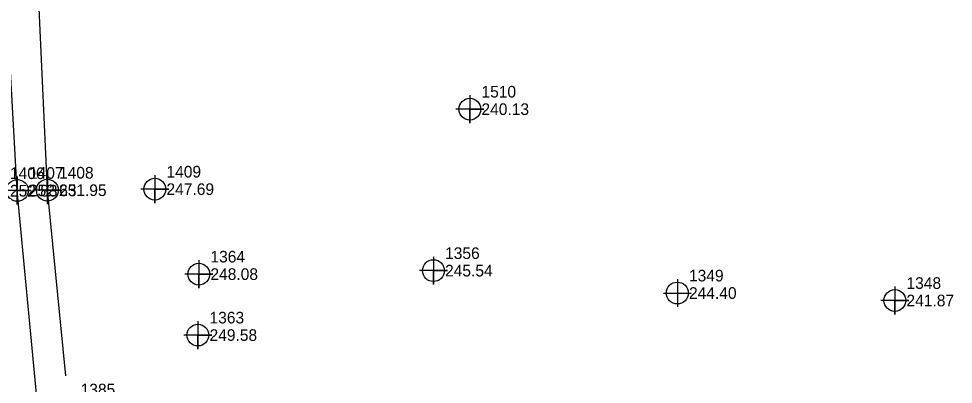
# Model space of a CAD drawing. Extents: x 2130962 to 2131465, y 643052 to 644206.
# Drawn here: x 2131260.2 to 2131460.9, y 643227.7 to 643306.2 of the extents above; entities that cross this region are included whole.
import ezdxf

# ---------------------------------------------------------------- set-up
doc = ezdxf.new("R2010")
doc.units = 0
for name, color, linetype in [('Exist DTM Breakline', 7, 'Continuous'), ('Exist DTM Breakline Cogo Elevation', 7, 'Continuous'), ('Exist DTM Breakline Cogo Number', 7, 'Continuous'), ('Exist DTM Breakline Cogo Point CELL', 7, 'Continuous'), ('Exist DTM Regular Point CELL', 7, 'Continuous'), ('Exist DTM Regular Point Cogo Elevation', 7, 'Continuous'), ('Exist DTM Regular Point Cogo Number', 7, 'Continuous'), ('Exist Roads EOP', 7, 'Continuous'), ('Exist Roads EOP Cogo Elevation', 7, 'Continuous'), ('Exist Roads EOP Cogo Number', 7, 'Continuous'), ('Exist Roads EOP Cogo Point CELL', 7, 'Continuous'), ('Exist Roads EOT Cogo Elevation', 7, 'Continuous'), ('Exist Roads EOT Cogo Number', 7, 'Continuous')]:
    doc.layers.add(name, color=color, linetype=linetype)

msp = doc.modelspace()

# ---------------------------------------------------------------- linework, layer by layer
at = {"layer": 'Exist DTM Breakline'}
msp.add_line((2131270.3119, 643229.444), (2131266.3306, 643269.372), dxfattribs=at)
msp.add_lwpolyline([(2131266.3306, 643269.372), (2131264.0776, 643319.4437), (2131258.8396, 643369.5498), (2131255.3671, 643419.5794), (2131249.6414, 643469.556), (2131244.7652, 643520.0623), (2131238.8778, 643569.4077), (2131228.6495, 643620.6699), (2131219.85, 643669.4823), (2131206.9682, 643717.8453), (2131195.8132, 643768.1497), (2131183.2404, 643816.8151), (2131169.0496, 643865.1461), (2131151.2314, 643913.4424), (2131130.7295, 643958.9736), (2131122.7411, 643983.0115)], dxfattribs=at)
at = {"layer": 'Exist DTM Breakline Cogo Point CELL'}
msp.add_lwpolyline([(2131266.3306, 643272.372), (2131266.3306, 643266.372), (2131266.3306, 643269.372), (2131269.3306, 643269.372), (2131263.3306, 643269.372)], dxfattribs=at)
msp.add_circle((2131266.3306, 643269.372), 2.344, dxfattribs=at)
at = {"layer": 'Exist DTM Regular Point CELL'}
for points in [[(2131357.0825, 643289.7878), (2131357.0825, 643283.7878), (2131357.0825, 643286.7878), (2131360.0825, 643286.7878), (2131354.0825, 643286.7878)], [(2131289.4176, 643272.5954), (2131289.4176, 643266.5954), (2131289.4176, 643269.5954), (2131292.4176, 643269.5954), (2131286.4176, 643269.5954)], [(2131298.8562, 643254.3369), (2131298.8562, 643248.3369), (2131298.8562, 643251.3369), (2131301.8562, 643251.3369), (2131295.8562, 643251.3369)], [(2131349.2628, 643255.0853), (2131349.2628, 643249.0853), (2131349.2628, 643252.0853), (2131352.2628, 643252.0853), (2131346.2628, 643252.0853)], [(2131401.6594, 643250.2687), (2131401.6594, 643247.2687)], [(2131398.6594, 643247.2687), (2131401.6594, 643247.2687)], [(2131401.6594, 643247.2687), (2131404.6594, 643247.2687)], [(2131401.6594, 643247.2687), (2131401.6594, 643244.2687)], [(2131448.3809, 643248.6638), (2131448.3809, 643242.6638), (2131448.3809, 643245.6638), (2131451.3809, 643245.6638), (2131445.3809, 643245.6638)], [(2131298.6665, 643241.234), (2131298.6665, 643235.234), (2131298.6665, 643238.234), (2131301.6665, 643238.234), (2131295.6665, 643238.234)]]:
    msp.add_lwpolyline(points, dxfattribs=at)
for centre in [(2131357.0825, 643286.7878), (2131289.4176, 643269.5954), (2131298.8562, 643251.3369), (2131349.2628, 643252.0853), (2131401.6594, 643247.2687), (2131448.3809, 643245.6638), (2131298.6665, 643238.234)]:
    msp.add_circle(centre, 2.344, dxfattribs=at)
at = {"layer": 'Exist Roads EOP'}
msp.add_lwpolyline([(2131264.2715, 643222.5647), (2131259.8757, 643269.3254), (2131257.0196, 643319.4043), (2131254.2561, 643369.6499), (2131250.0777, 643419.4187), (2131246.1511, 643469.0294), (2131240.8382, 643519.1271), (2131234.3674, 643568.5584), (2131226.3321, 643620.1808), (2131217.0271, 643668.7116), (2131205.6213, 643717.607), (2131192.0578, 643767.2595), (2131177.9714, 643815.0911), (2131162.2913, 643862.9344), (2131145.3604, 643910.8486), (2131126.9113, 643957.2915), (2131112.3691, 643996.1228)], dxfattribs=at)
at = {"layer": 'Exist Roads EOP Cogo Point CELL'}
msp.add_lwpolyline([(2131259.8757, 643272.3254), (2131259.8757, 643266.3254), (2131259.8757, 643269.3254), (2131262.8757, 643269.3254), (2131256.8757, 643269.3254)], dxfattribs=at)
msp.add_circle((2131259.8757, 643269.3254), 2.344, dxfattribs=at)

# ---------------------------------------------------------------- texts
at = {"layer": 'Exist DTM Breakline Cogo Elevation'}
msp.add_text('251.95', height=2.5, dxfattribs=at).set_placement((2131268.8306, 643268.122))
at = {"layer": 'Exist DTM Breakline Cogo Number'}
for s, p in [('1408', (2131268.8306, 643271.872)), ('1385', (2131273.4763, 643225.2805))]:
    msp.add_text(s, height=2.5, dxfattribs=at).set_placement(p)
at = {"layer": 'Exist DTM Regular Point Cogo Elevation'}
for s, p in [('240.13', (2131359.5825, 643285.5378)), ('247.69', (2131291.9176, 643268.3454)), ('245.54', (2131351.7628, 643250.8353)), ('248.08', (2131301.3562, 643250.0869)), ('244.40', (2131404.1594, 643246.0187)), ('241.87', (2131450.8809, 643244.4138)), ('249.58', (2131301.1665, 643236.984))]:
    msp.add_text(s, height=2.5, dxfattribs=at).set_placement(p)
at = {"layer": 'Exist DTM Regular Point Cogo Number'}
for s, p in [('1510', (2131359.5825, 643289.2878)), ('1409', (2131291.9176, 643272.0954)), ('1364', (2131301.3562, 643253.8369)), ('1356', (2131351.7628, 643254.5853)), ('1349', (2131404.1594, 643249.7687)), ('1348', (2131450.8809, 643248.1638)), ('1363', (2131301.1665, 643240.734))]:
    msp.add_text(s, height=2.5, dxfattribs=at).set_placement(p)
at = {"layer": 'Exist Roads EOP Cogo Elevation'}
msp.add_text('252.63', height=2.5, dxfattribs=at).set_placement((2131262.3757, 643268.0754))
at = {"layer": 'Exist Roads EOP Cogo Number'}
msp.add_text('1407', height=2.5, dxfattribs=at).set_placement((2131262.3757, 643271.8254))
at = {"layer": 'Exist Roads EOT Cogo Elevation'}
msp.add_text('252.83', height=2.5, dxfattribs=at).set_placement((2131258.2894, 643268.0166))
at = {"layer": 'Exist Roads EOT Cogo Number'}
msp.add_text('1406', height=2.5, dxfattribs=at).set_placement((2131258.2894, 643271.7666))

doc.saveas('drawing.dxf')
